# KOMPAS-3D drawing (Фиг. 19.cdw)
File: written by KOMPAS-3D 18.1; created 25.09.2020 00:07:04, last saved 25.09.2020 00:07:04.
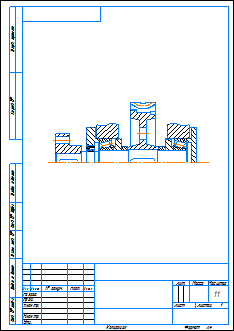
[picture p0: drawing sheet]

Sheet 1: A4, portrait

Document properties: Автор: user; Полное имя файла: C:\Users\user\Desktop\Задания\Фиг. 19.cdw

Title block, sheet 1: scale: 1:1; Количество листов документа: 1; Форматы листов документа: A4

Dimensions and other numbers on the sheet: 1:1; 1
